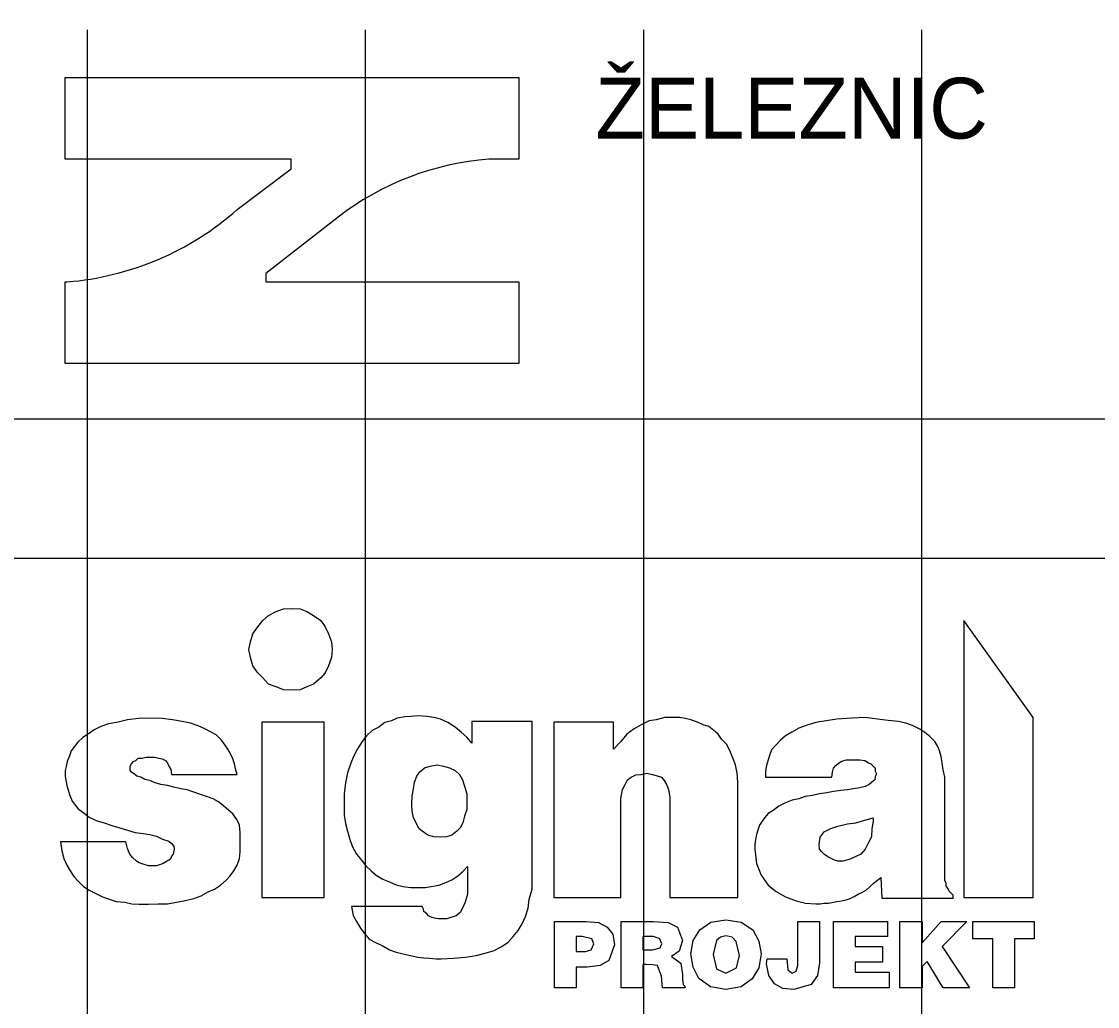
# Model space of a CAD drawing. Extents: x -1442 to 8065, y -772 to 6486.
# Drawn here: x 2542.64 to 2581.32, y 623.88 to 659.29 of the extents above; entities that cross this region are included whole.
import ezdxf

# ---------------------------------------------------------------- set-up
doc = ezdxf.new("R2010")
doc.units = 0
for name, color, linetype in [('Info o rozpiskách', 7, 'Continuous'), ('popis', 7, 'Continuous'), ('Rozpiska_Logo', 7, 'Continuous'), ('Rozpiska_pole_5', 7, 'Continuous'), ('Rozpiska_pole_6', 7, 'Continuous')]:
    doc.layers.add(name, color=color, linetype=linetype)

msp = doc.modelspace()

# ---------------------------------------------------------------- linework, layer by layer
for p, q in [((2545, 659), (2545, 569)), ((2555, 659), (2555, 569)), ((2565, 659), (2565, 569)), ((2575, 659), (2575, 569))]:
    msp.add_line(p, q)
at = {"layer": 'Info o rozpiskách'}
for points in [[(2552.382, 638.197), (2552.662, 638.178), (2552.903, 638.078), (2553.143, 637.937), (2553.403, 637.757), (2553.563, 637.537), (2553.684, 637.276), (2553.784, 636.996), (2553.804, 636.715), (2553.784, 636.435), (2553.684, 636.134), (2553.563, 635.874), (2553.403, 635.694), (2553.143, 635.473), (2552.903, 635.373), (2552.662, 635.273), (2552.382, 635.253), (2552.061, 635.273), (2551.801, 635.373), (2551.52, 635.473), (2551.32, 635.694), (2551.14, 635.874), (2550.959, 636.134), (2550.879, 636.435), (2550.819, 636.715), (2550.879, 636.996), (2550.959, 637.276), (2551.14, 637.537), (2551.32, 637.757), (2551.52, 637.937), (2551.801, 638.078), (2552.061, 638.178), (2552.382, 638.197)], [(2567.967, 626.999), (2568.508, 626.919), (2568.929, 626.639), (2569.149, 626.238), (2569.229, 625.778), (2569.149, 625.277), (2568.908, 624.876), (2568.508, 624.596), (2567.967, 624.496), (2567.406, 624.596), (2566.985, 624.896), (2566.785, 625.297), (2566.705, 625.778), (2566.785, 626.258), (2567.025, 626.639), (2567.426, 626.919), (2567.967, 626.999)], [(2561.797, 626.94), (2562.939, 626.94), (2563.379, 626.899), (2563.7, 626.739), (2563.9, 626.478), (2563.96, 626.098), (2563.76, 625.537), (2563.439, 625.356), (2562.979, 625.297), (2562.578, 625.297), (2562.578, 624.555), (2561.797, 624.555), (2561.797, 626.94)], [(2564.201, 626.94), (2565.363, 626.94), (2565.883, 626.899), (2566.224, 626.739), (2566.404, 626.258), (2566.284, 625.878), (2566.004, 625.677), (2566.344, 625.437), (2566.404, 625.036), (2566.404, 624.856), (2566.424, 624.675), (2566.485, 624.615), (2566.485, 624.555), (2565.683, 624.555), (2565.643, 624.976), (2565.503, 625.356), (2565.342, 625.377), (2565.102, 625.397), (2564.982, 625.397), (2564.982, 624.555), (2564.201, 624.555), (2564.201, 626.94)], [(2570.55, 626.94), (2571.332, 626.94), (2571.332, 625.457), (2571.251, 624.996), (2571.031, 624.675), (2570.41, 624.496), (2570.009, 624.536), (2569.709, 624.696), (2569.509, 624.996), (2569.428, 625.417), (2569.448, 625.597), (2570.15, 625.597), (2570.19, 625.196), (2570.35, 625.077), (2570.49, 625.156), (2570.55, 625.356), (2570.55, 626.94)], [(2571.832, 626.94), (2573.776, 626.94), (2573.776, 626.399), (2572.613, 626.399), (2572.613, 626.038), (2573.595, 626.038), (2573.595, 625.477), (2572.613, 625.477), (2572.613, 625.116), (2573.835, 625.116), (2573.835, 624.555), (2571.832, 624.555), (2571.832, 626.94)], [(2574.216, 626.94), (2575.017, 626.94), (2575.017, 626.178), (2575.698, 626.94), (2576.62, 626.94), (2575.739, 626.038), (2576.72, 624.555), (2575.779, 624.555), (2575.198, 625.497), (2575.017, 625.317), (2575.017, 624.555), (2574.216, 624.555), (2574.216, 626.94)], [(2576.841, 626.94), (2579.044, 626.94), (2579.044, 626.318), (2578.343, 626.318), (2578.343, 624.555), (2577.561, 624.555), (2577.561, 626.318), (2576.841, 626.318), (2576.841, 626.94)], [(2562.578, 626.399), (2562.578, 625.858), (2562.919, 625.858), (2563.119, 625.918), (2563.219, 626.138), (2563.139, 626.318), (2562.798, 626.399), (2562.578, 626.399)], [(2564.982, 626.399), (2564.982, 625.918), (2565.323, 625.918), (2565.603, 625.997), (2565.663, 626.138), (2565.583, 626.318), (2565.363, 626.399), (2564.982, 626.399)], [(2567.967, 626.418), (2567.767, 626.378), (2567.626, 626.258), (2567.506, 625.758), (2567.626, 625.237), (2567.967, 625.077), (2568.348, 625.277), (2568.448, 625.718), (2568.327, 626.218), (2568.188, 626.378), (2567.967, 626.418)]]:
    msp.add_lwpolyline(points, dxfattribs=at)
at = {"layer": 'popis'}
for points in [[(2576.52, 637.757), (2576.52, 627.8), (2579.004, 627.8), (2579.004, 634.271), (2576.52, 637.757)], [(2558.832, 634.131), (2558.832, 633.35), (2558.651, 633.57), (2558.451, 633.75), (2558.231, 633.931), (2557.97, 634.091), (2557.71, 634.211), (2557.47, 634.271), (2557.209, 634.312), (2556.909, 634.331), (2556.628, 634.312), (2556.428, 634.291), (2556.148, 634.251), (2555.947, 634.151), (2555.707, 634.091), (2555.487, 633.931), (2555.246, 633.81), (2555.046, 633.61), (2554.885, 633.41), (2554.725, 633.15), (2554.585, 632.889), (2554.485, 632.628), (2554.365, 632.288), (2554.285, 631.928), (2554.244, 631.527), (2554.244, 631.106), (2554.244, 630.765), (2554.285, 630.465), (2554.365, 630.184), (2554.445, 629.884), (2554.545, 629.624), (2554.685, 629.363), (2554.866, 629.143), (2555.026, 628.943), (2555.206, 628.762), (2555.387, 628.602), (2555.626, 628.462), (2555.867, 628.362), (2556.107, 628.262), (2556.368, 628.202), (2556.628, 628.161), (2556.909, 628.161), (2557.15, 628.161), (2557.37, 628.202), (2557.65, 628.241), (2557.891, 628.341), (2558.111, 628.441), (2558.331, 628.582), (2558.491, 628.722), (2558.672, 628.922), (2558.672, 628.341), (2558.672, 627.921), (2558.591, 627.64), (2558.491, 627.42), (2558.411, 627.26), (2558.271, 627.14), (2558.111, 627.1), (2557.931, 627.04), (2557.731, 627.04), (2557.63, 627.04), (2557.49, 627.059), (2557.37, 627.1), (2557.269, 627.14), (2557.209, 627.219), (2557.109, 627.3), (2557.089, 627.38), (2557.049, 627.48), (2554.505, 627.48), (2554.565, 627.159), (2554.685, 626.94), (2554.825, 626.699), (2554.966, 626.519), (2555.146, 626.299), (2555.387, 626.178), (2555.607, 626.078), (2555.867, 625.918), (2556.107, 625.837), (2556.368, 625.778), (2556.609, 625.718), (2556.889, 625.658), (2557.109, 625.637), (2557.31, 625.617), (2557.55, 625.597), (2557.731, 625.597), (2558.171, 625.617), (2558.591, 625.658), (2558.992, 625.718), (2559.313, 625.797), (2559.633, 625.897), (2559.914, 626.038), (2560.134, 626.198), (2560.314, 626.399), (2560.495, 626.619), (2560.635, 626.859), (2560.755, 627.119), (2560.855, 627.42), (2560.895, 627.741), (2560.995, 628.102), (2560.995, 628.482), (2560.995, 628.922), (2560.995, 634.131), (2558.832, 634.131)], [(2548.034, 632.228), (2550.398, 632.228), (2550.338, 632.428), (2550.298, 632.609), (2550.238, 632.788), (2550.158, 632.969), (2550.057, 633.129), (2549.938, 633.31), (2549.818, 633.47), (2549.637, 633.65), (2549.457, 633.75), (2549.237, 633.871), (2548.996, 633.971), (2548.716, 634.071), (2548.415, 634.131), (2548.075, 634.191), (2547.694, 634.231), (2547.274, 634.251), (2546.853, 634.231), (2546.452, 634.191), (2546.112, 634.111), (2545.771, 634.051), (2545.49, 633.951), (2545.25, 633.831), (2545.05, 633.69), (2544.849, 633.55), (2544.669, 633.39), (2544.549, 633.229), (2544.428, 633.069), (2544.369, 632.889), (2544.288, 632.688), (2544.249, 632.509), (2544.208, 632.368), (2544.208, 632.147), (2544.268, 631.827), (2544.369, 631.507), (2544.469, 631.266), (2544.669, 631.006), (2544.849, 630.866), (2545.069, 630.685), (2545.33, 630.565), (2545.61, 630.485), (2545.891, 630.385), (2546.172, 630.305), (2546.452, 630.225), (2546.732, 630.144), (2547.013, 630.105), (2547.253, 630.065), (2547.494, 630.004), (2547.714, 629.904), (2547.934, 629.824), (2548.034, 629.744), (2548.115, 629.644), (2548.135, 629.544), (2548.094, 629.363), (2548.034, 629.283), (2547.994, 629.183), (2547.874, 629.103), (2547.734, 629.022), (2547.634, 628.983), (2547.494, 628.943), (2547.353, 628.943), (2547.213, 628.943), (2547.053, 628.983), (2546.872, 629.043), (2546.772, 629.103), (2546.632, 629.243), (2546.532, 629.363), (2546.452, 629.563), (2546.392, 629.804), (2544.048, 629.804), (2544.088, 629.484), (2544.168, 629.203), (2544.268, 628.962), (2544.388, 628.762), (2544.529, 628.562), (2544.689, 628.381), (2544.869, 628.202), (2545.069, 628.061), (2545.31, 627.941), (2545.55, 627.821), (2545.791, 627.741), (2546.051, 627.661), (2546.352, 627.64), (2546.612, 627.58), (2546.872, 627.56), (2547.213, 627.56), (2547.554, 627.58), (2547.894, 627.58), (2548.215, 627.64), (2548.535, 627.7), (2548.835, 627.761), (2549.096, 627.861), (2549.357, 628.001), (2549.577, 628.102), (2549.797, 628.241), (2549.998, 628.422), (2550.138, 628.582), (2550.278, 628.762), (2550.398, 628.962), (2550.478, 629.203), (2550.499, 629.443), (2550.499, 629.684), (2550.499, 629.744), (2550.499, 629.804), (2550.499, 629.864), (2550.499, 629.924), (2550.499, 630.004), (2550.499, 630.065), (2550.499, 630.105), (2550.499, 630.144), (2550.478, 630.405), (2550.378, 630.605), (2550.238, 630.806), (2550.078, 630.946), (2549.918, 631.086), (2549.718, 631.246), (2549.537, 631.347), (2549.297, 631.427), (2549.076, 631.507), (2548.835, 631.587), (2548.596, 631.667), (2548.375, 631.707), (2548.115, 631.767), (2547.894, 631.827), (2547.654, 631.868), (2547.453, 631.928), (2547.253, 632.007), (2547.073, 632.047), (2546.933, 632.128), (2546.793, 632.168), (2546.712, 632.228), (2546.593, 632.308), (2546.552, 632.368), (2546.552, 632.448), (2546.552, 632.528), (2546.593, 632.609), (2546.672, 632.688), (2546.753, 632.729), (2546.832, 632.809), (2546.973, 632.809), (2547.133, 632.849), (2547.274, 632.849), (2547.434, 632.849), (2547.574, 632.809), (2547.694, 632.788), (2547.814, 632.729), (2547.894, 632.628), (2547.934, 632.528), (2548.015, 632.408), (2548.034, 632.228)], [(2551.28, 634.111), (2551.28, 627.8), (2553.523, 627.8), (2553.523, 634.111), (2551.28, 634.111)], [(2561.776, 634.111), (2561.776, 627.8), (2564.181, 627.8), (2564.181, 631.026), (2564.181, 631.366), (2564.241, 631.687), (2564.341, 631.868), (2564.421, 632.028), (2564.561, 632.128), (2564.722, 632.208), (2564.922, 632.228), (2565.122, 632.268), (2565.323, 632.228), (2565.463, 632.188), (2565.643, 632.128), (2565.744, 632.007), (2565.823, 631.868), (2565.904, 631.687), (2565.944, 631.406), (2565.944, 631.126), (2565.944, 627.8), (2568.388, 627.8), (2568.388, 631.607), (2568.388, 631.947), (2568.367, 632.268), (2568.307, 632.568), (2568.207, 632.849), (2568.107, 633.09), (2567.986, 633.31), (2567.807, 633.49), (2567.686, 633.671), (2567.526, 633.81), (2567.346, 633.951), (2567.145, 634.01), (2566.945, 634.111), (2566.705, 634.191), (2566.504, 634.231), (2566.304, 634.271), (2566.064, 634.271), (2565.763, 634.271), (2565.463, 634.191), (2565.202, 634.151), (2564.922, 634.01), (2564.661, 633.871), (2564.401, 633.671), (2564.181, 633.41), (2563.92, 633.129), (2563.92, 634.111), (2561.776, 634.111)], [(2569.388, 632.128), (2571.772, 632.128), (2571.792, 632.308), (2571.832, 632.448), (2571.913, 632.549), (2572.013, 632.628), (2572.133, 632.709), (2572.293, 632.749), (2572.433, 632.749), (2572.594, 632.749), (2572.773, 632.749), (2572.954, 632.729), (2573.094, 632.649), (2573.175, 632.609), (2573.254, 632.528), (2573.335, 632.448), (2573.335, 632.348), (2573.375, 632.248), (2573.335, 632.147), (2573.315, 632.028), (2573.214, 631.947), (2573.114, 631.868), (2572.975, 631.787), (2572.773, 631.747), (2572.553, 631.707), (2572.333, 631.667), (2572.092, 631.647), (2571.832, 631.607), (2571.592, 631.566), (2571.332, 631.527), (2571.071, 631.466), (2570.81, 631.427), (2570.59, 631.347), (2570.35, 631.306), (2570.11, 631.206), (2569.869, 631.086), (2569.669, 630.926), (2569.488, 630.825), (2569.348, 630.665), (2569.249, 630.505), (2569.169, 630.405), (2569.108, 630.225), (2569.069, 630.065), (2569.029, 629.884), (2569.008, 629.724), (2569.008, 629.544), (2569.069, 629.022), (2569.229, 628.602), (2569.488, 628.241), (2569.769, 628.021), (2570.11, 627.821), (2570.49, 627.681), (2570.831, 627.6), (2571.191, 627.58), (2571.351, 627.58), (2571.492, 627.6), (2571.652, 627.6), (2571.832, 627.64), (2571.953, 627.661), (2572.133, 627.681), (2572.293, 627.721), (2572.433, 627.761), (2572.573, 627.841), (2572.714, 627.921), (2572.854, 627.981), (2573.014, 628.081), (2573.135, 628.181), (2573.254, 628.302), (2573.415, 628.422), (2573.535, 628.522), (2573.575, 627.781), (2576.139, 627.781), (2576.139, 627.881), (2575.999, 628.021), (2575.939, 628.121), (2575.879, 628.221), (2575.879, 628.302), (2575.839, 628.422), (2575.839, 628.502), (2575.839, 628.622), (2575.839, 628.782), (2575.839, 631.868), (2575.839, 632.128), (2575.779, 632.388), (2575.739, 632.628), (2575.698, 632.869), (2575.638, 633.069), (2575.578, 633.229), (2575.478, 633.41), (2575.298, 633.59), (2575.117, 633.731), (2574.938, 633.85), (2574.697, 633.971), (2574.436, 634.071), (2574.156, 634.131), (2573.795, 634.171), (2573.415, 634.211), (2572.975, 634.271), (2572.473, 634.251), (2571.953, 634.211), (2571.572, 634.151), (2571.191, 634.091), (2570.851, 633.991), (2570.59, 633.891), (2570.33, 633.75), (2570.11, 633.61), (2569.909, 633.45), (2569.769, 633.29), (2569.609, 633.109), (2569.529, 632.909), (2569.488, 632.749), (2569.428, 632.549), (2569.388, 632.348), (2569.388, 632.128)], [(2557.59, 632.568), (2557.81, 632.528), (2558.031, 632.468), (2558.231, 632.368), (2558.391, 632.228), (2558.491, 632.028), (2558.572, 631.807), (2558.651, 631.527), (2558.651, 631.226), (2558.651, 630.966), (2558.572, 630.725), (2558.512, 630.485), (2558.411, 630.305), (2558.291, 630.184), (2558.111, 630.044), (2557.931, 629.984), (2557.69, 629.965), (2557.45, 629.984), (2557.25, 630.044), (2557.049, 630.184), (2556.929, 630.285), (2556.829, 630.485), (2556.729, 630.665), (2556.688, 630.906), (2556.669, 631.166), (2556.688, 631.447), (2556.729, 631.707), (2556.769, 631.947), (2556.848, 632.168), (2556.949, 632.308), (2557.129, 632.468), (2557.329, 632.528), (2557.59, 632.568)], [(2573.254, 630.665), (2573.254, 630.646), (2573.254, 630.585), (2573.254, 630.546), (2573.214, 630.265), (2573.194, 629.984), (2573.094, 629.784), (2572.975, 629.544), (2572.814, 629.363), (2572.613, 629.263), (2572.393, 629.163), (2572.173, 629.103), (2571.992, 629.103), (2571.872, 629.143), (2571.753, 629.203), (2571.632, 629.263), (2571.512, 629.343), (2571.412, 629.443), (2571.332, 629.544), (2571.312, 629.704), (2571.351, 629.965), (2571.492, 630.165), (2571.732, 630.285), (2571.992, 630.365), (2572.333, 630.445), (2572.634, 630.485), (2572.954, 630.585), (2573.254, 630.665)]]:
    msp.add_lwpolyline(points, dxfattribs=at)
at = {"layer": 'Rozpiska_Logo'}
for p, q in [((2552.337, 653.994), (2552.337, 654.341)), ((2550.398, 652.532), (2552.337, 653.994)), ((2554.03, 652.262), (2551.421, 650.24)), ((2551.421, 650.24), (2551.421, 649.934))]:
    msp.add_line(p, q, dxfattribs=at)
for points in [[(2552.337, 654.341), (2544.216, 654.341), (2544.216, 657.275), (2560.517, 657.275), (2560.517, 654.341), (2559.445, 654.341)], [(2551.421, 649.934), (2560.517, 649.934), (2560.517, 647), (2544.216, 647), (2544.216, 649.934), (2544.283, 649.934)]]:
    msp.add_lwpolyline(points, dxfattribs=at)
for centre, radius, start, end in [((2560.183, 644.325), 10.043, 94.2142, 127.7808), ((2543.439, 660.418), 10.518, 274.6014, 311.4254)]:
    msp.add_arc(centre, radius, start, end, dxfattribs=at)
at = {"layer": 'Rozpiska_pole_5'}
msp.add_lwpolyline([(2430, 665), (2600, 665), (2600, 645), (2430, 645)], close=True, dxfattribs=at)
at = {"layer": 'Rozpiska_pole_6'}
msp.add_lwpolyline([(2430, 640), (2600, 640), (2600, 600), (2430, 600)], close=True, dxfattribs=at)

# ---------------------------------------------------------------- texts
msp.add_text('ŽELEZNIC', height=2.1832, dxfattribs=at).set_placement((2563.268, 655.086))

doc.saveas('drawing.dxf')
